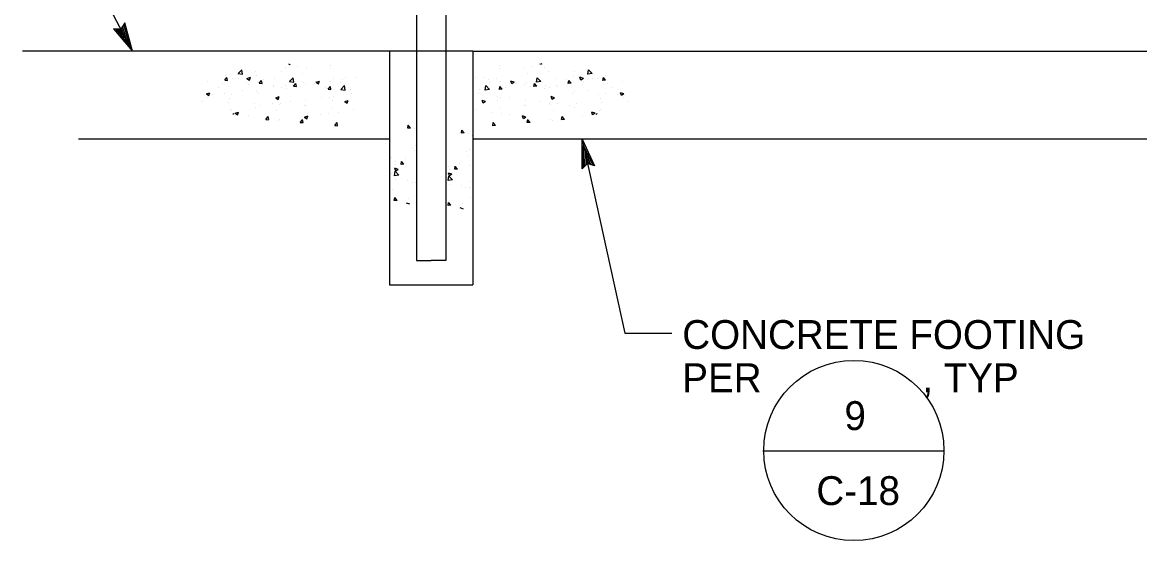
# Model space of a CAD drawing. Extents: x -123486 to -116575, y -107066 to -101122.
# Drawn here: x -118888.8 to -118656.4, y -103159.5 to -103051.7 of the extents above; entities that cross this region are included whole.
import ezdxf

# ---------------------------------------------------------------- set-up
doc = ezdxf.new("R2010")
doc.units = 0
for name, color, linetype in [('Erosion C (Lv35)', 7, 'Continuous'), ('G-MARK', 7, 'Continuous'), ('Misc CnstDet(22)', 7, 'Continuous')]:
    doc.layers.add(name, color=color, linetype=linetype)

# ---------------------------------------------------------------- blocks, each defined once
blk = doc.blocks.new('SC8415')
at = {"layer": 'Erosion C (Lv35)'}
for p, q in [((-1.69606, 1.76963), (-1.69579, 1.76945)), ((-1.69579, 1.76945), (-1.69573, 1.76963)), ((-1.69408, 1.76913), (-1.69408, 1.76913)), ((-1.68715, 1.76926), (-1.68715, 1.76926)), ((-1.70955, 1.76614), (-1.70906, 1.76672)), ((-1.70943, 1.76711), (-1.70943, 1.76711)), ((-1.70894, 1.76609), (-1.70906, 1.76672)), ((-1.70689, 1.76745), (-1.70689, 1.76745)), ((-1.70669, 1.76754), (-1.7059, 1.76836)), ((-1.70669, 1.76754), (-1.70579, 1.7674)), ((-1.70579, 1.7674), (-1.7059, 1.76836)), ((-1.70484, 1.76651), (-1.70412, 1.76679)), ((-1.70433, 1.76617), (-1.70412, 1.76679)), ((-1.70304, 1.76795), (-1.70304, 1.76795)), ((-1.70278, 1.76714), (-1.70278, 1.76714)), ((-1.6975, 1.7679), (-1.6975, 1.7679)), ((-1.69662, 1.7688), (-1.69662, 1.7688)), ((-1.69585, 1.76586), (-1.69506, 1.76668)), ((-1.69494, 1.76572), (-1.69506, 1.76668)), ((-1.69309, 1.7676), (-1.69309, 1.7676)), ((-1.69228, 1.76861), (-1.69228, 1.76861)), ((-1.68716, 1.76862), (-1.68716, 1.76862)), ((-1.68394, 1.76681), (-1.68394, 1.76681)), ((-1.682, 1.76664), (-1.682, 1.76664)), ((-1.71312, 1.76577), (-1.71312, 1.76577)), ((-1.71086, 1.76455), (-1.71086, 1.76455)), ((-1.71, 1.76543), (-1.71, 1.76543)), ((-1.70955, 1.76614), (-1.70894, 1.76608)), ((-1.70791, 1.76649), (-1.70791, 1.76649)), ((-1.70672, 1.76656), (-1.70672, 1.76656)), ((-1.70494, 1.76557), (-1.70494, 1.76557)), ((-1.70484, 1.76651), (-1.70433, 1.76617)), ((-1.70458, 1.7652), (-1.70458, 1.7652)), ((-1.70226, 1.7655), (-1.70177, 1.76608)), ((-1.70226, 1.7655), (-1.70165, 1.76545)), ((-1.70165, 1.76545), (-1.70177, 1.76609)), ((-1.7013, 1.76633), (-1.7013, 1.76633)), ((-1.6993, 1.76479), (-1.6993, 1.76479)), ((-1.69916, 1.76497), (-1.69916, 1.76497)), ((-1.69901, 1.76659), (-1.69901, 1.76659)), ((-1.69762, 1.76452), (-1.69762, 1.76452)), ((-1.69675, 1.76513), (-1.69675, 1.76513)), ((-1.69658, 1.76435), (-1.69658, 1.76435)), ((-1.69588, 1.7661), (-1.69588, 1.7661)), ((-1.69585, 1.76586), (-1.69494, 1.76572)), ((-1.69497, 1.76486), (-1.69449, 1.76545)), ((-1.69497, 1.76486), (-1.69437, 1.76481)), ((-1.69437, 1.76481), (-1.69448, 1.76545)), ((-1.69373, 1.76474), (-1.69373, 1.76474)), ((-1.6929, 1.76563), (-1.6929, 1.76563)), ((-1.69241, 1.76523), (-1.69241, 1.76523)), ((-1.69065, 1.76537), (-1.69065, 1.76537)), ((-1.69045, 1.76587), (-1.69045, 1.76587)), ((-1.69023, 1.7657), (-1.68952, 1.76597)), ((-1.69023, 1.7657), (-1.68973, 1.76536)), ((-1.68973, 1.76536), (-1.68952, 1.76597)), ((-1.68831, 1.76451), (-1.68831, 1.76451)), ((-1.68769, 1.76423), (-1.6872, 1.76481)), ((-1.68727, 1.76588), (-1.68727, 1.76588)), ((-1.68708, 1.76417), (-1.6872, 1.76481)), ((-1.68649, 1.76648), (-1.68649, 1.76648)), ((-1.68503, 1.76565), (-1.68503, 1.76565)), ((-1.685, 1.76418), (-1.68421, 1.765)), ((-1.68473, 1.76639), (-1.68473, 1.76639)), ((-1.6841, 1.76404), (-1.68421, 1.765)), ((-1.68289, 1.76428), (-1.68289, 1.76428)), ((-1.71337, 1.76324), (-1.71266, 1.76351)), ((-1.71337, 1.76324), (-1.71287, 1.7629)), ((-1.71325, 1.76239), (-1.71325, 1.76239)), ((-1.71287, 1.7629), (-1.71266, 1.76351)), ((-1.7121, 1.7631), (-1.7121, 1.7631)), ((-1.70956, 1.76344), (-1.70956, 1.76344)), ((-1.70843, 1.76232), (-1.70843, 1.76232)), ((-1.70803, 1.7631), (-1.70803, 1.7631)), ((-1.70571, 1.76395), (-1.70571, 1.76395)), ((-1.7029, 1.76375), (-1.7029, 1.76375)), ((-1.7025, 1.76334), (-1.7025, 1.76334)), ((-1.69877, 1.76242), (-1.69806, 1.7627)), ((-1.69877, 1.76242), (-1.69827, 1.76208)), ((-1.69826, 1.76208), (-1.69806, 1.7627)), ((-1.68916, 1.76247), (-1.68916, 1.76247)), ((-1.68769, 1.76423), (-1.68708, 1.76417)), ((-1.6874, 1.7625), (-1.6874, 1.7625)), ((-1.68662, 1.7628), (-1.68662, 1.7628)), ((-1.685, 1.76418), (-1.6841, 1.76404)), ((-1.68277, 1.76331), (-1.68277, 1.76331)), ((-1.71417, 1.76163), (-1.71417, 1.76163)), ((-1.70874, 1.7614), (-1.70874, 1.7614)), ((-1.70839, 1.75994), (-1.70839, 1.75994)), ((-1.70815, 1.75972), (-1.70815, 1.75972)), ((-1.70332, 1.76117), (-1.70332, 1.76117)), ((-1.70302, 1.76037), (-1.70302, 1.76037)), ((-1.70197, 1.76078), (-1.70197, 1.76078)), ((-1.69943, 1.76112), (-1.69943, 1.76112)), ((-1.69862, 1.75978), (-1.69862, 1.75978)), ((-1.6979, 1.76094), (-1.6979, 1.76094)), ((-1.69775, 1.76113), (-1.69775, 1.76113)), ((-1.69558, 1.76162), (-1.69558, 1.76162)), ((-1.6927, 1.7608), (-1.6927, 1.7608)), ((-1.69253, 1.76185), (-1.69253, 1.76185)), ((-1.69247, 1.76071), (-1.69247, 1.76071)), ((-1.68705, 1.76048), (-1.68705, 1.76048)), ((-1.68677, 1.76182), (-1.68677, 1.76182)), ((-1.68417, 1.76161), (-1.68346, 1.76188)), ((-1.68417, 1.76161), (-1.68366, 1.76127)), ((-1.68366, 1.76127), (-1.68346, 1.76188)), ((-1.68224, 1.75988), (-1.68224, 1.75988)), ((-1.70775, 1.75896), (-1.70765, 1.75908)), ((-1.70762, 1.7589), (-1.70765, 1.75908)), ((-1.70731, 1.75915), (-1.7066, 1.75942)), ((-1.70731, 1.75915), (-1.7068, 1.75881)), ((-1.7068, 1.75881), (-1.7066, 1.75942)), ((-1.70455, 1.75876), (-1.70455, 1.75876)), ((-1.70085, 1.75786), (-1.70036, 1.75844)), ((-1.70085, 1.75786), (-1.70025, 1.7578)), ((-1.70024, 1.75781), (-1.70036, 1.75844)), ((-1.69825, 1.75762), (-1.69825, 1.75762)), ((-1.69787, 1.75775), (-1.69787, 1.75775)), ((-1.69357, 1.75722), (-1.69308, 1.7578)), ((-1.69357, 1.75722), (-1.69296, 1.75717)), ((-1.69296, 1.75717), (-1.69307, 1.75781)), ((-1.69271, 1.75833), (-1.692, 1.75861)), ((-1.69271, 1.75833), (-1.6922, 1.75799)), ((-1.69265, 1.75847), (-1.69265, 1.75847)), ((-1.6922, 1.75799), (-1.69199, 1.75861)), ((-1.69183, 1.75846), (-1.69183, 1.75846)), ((-1.68929, 1.7588), (-1.68929, 1.7588)), ((-1.68752, 1.75912), (-1.68752, 1.75912)), ((-1.68544, 1.7593), (-1.68544, 1.7593)), ((-1.68628, 1.75658), (-1.68579, 1.75717)), ((-1.68628, 1.75658), (-1.68567, 1.75653)), ((-1.68567, 1.75653), (-1.68579, 1.75717))]:
    blk.add_line(p, q, dxfattribs=at)

msp = doc.modelspace()

# ---------------------------------------------------------------- linework, layer by layer
at = {"layer": 'G-MARK'}
for p, q in [((-118865.89, -103057.71), (-118875.41, -103039.76)), ((-118868.33, -103053.12), (-118869.89, -103053.04)), ((-118869.89, -103053.04), (-118869.89, -103053.04)), ((-118869.89, -103053.04), (-118865.89, -103057.71)), ((-118869.47, -103053.06), (-118866.54, -103056.49)), ((-118869.04, -103053.1), (-118867.19, -103055.27)), ((-118868.66, -103053.09), (-118867.84, -103054.05)), ((-118867.53, -103051.79), (-118868.33, -103053.12)), ((-118867.84, -103054.05), (-118868.17, -103052.86)), ((-118867.19, -103055.27), (-118867.96, -103052.48)), ((-118866.54, -103056.48), (-118867.74, -103052.16)), ((-118865.89, -103057.71), (-118867.53, -103051.79)), ((-118867.53, -103051.79), (-118867.53, -103051.79)), ((-118865.89, -103057.71), (-118865.89, -103057.71)), ((-118772.38, -103082.15), (-118772.36, -103076)), ((-118772.36, -103076), (-118763.49, -103116.38)), ((-118772.36, -103076), (-118772.36, -103076)), ((-118772.36, -103076), (-118769.77, -103081.57)), ((-118772.08, -103081.86), (-118772.06, -103077.35)), ((-118772.06, -103077.36), (-118770.17, -103081.42)), ((-118771.78, -103081.55), (-118771.77, -103078.7)), ((-118771.77, -103078.7), (-118770.55, -103081.32)), ((-118771.24, -103081.08), (-118772.38, -103082.15)), ((-118771.48, -103081.31), (-118771.47, -103080.05)), ((-118771.47, -103080.05), (-118770.95, -103081.17)), ((-118769.77, -103081.57), (-118771.24, -103081.08)), ((-118769.77, -103081.57), (-118769.77, -103081.57)), ((-118772.38, -103082.15), (-118772.38, -103082.15)), ((-118763.49, -103116.38), (-118753.69, -103116.38)), ((-118734.78, -103140.84), (-118697.08, -103140.84))]:
    msp.add_line(p, q, dxfattribs=at)
msp.add_circle((-118715.83, -103140.79), 18.75, dxfattribs=at)
at = {"layer": 'Misc CnstDet(22)'}
for p, q in [((-118800.72, -102947.98), (-118800.72, -103101.22)), ((-118806.81, -102960.17), (-118806.81, -103101.22)), ((-118812.43, -103057.71), (-118888.83, -103057.71)), ((-118855.01, -103057.71), (-118877.35, -103057.71)), ((-118875.63, -103057.71), (-118875.63, -103057.71)), ((-118855.01, -103057.71), (-118860.95, -103057.71)), ((-118859.24, -103057.71), (-118859.24, -103057.71)), ((-118853.29, -103057.71), (-118853.29, -103057.71)), ((-118853.29, -103057.71), (-118853.29, -103057.71)), ((-118812.43, -103057.71), (-118812.43, -103094.29)), ((-118795.1, -103057.71), (-118812.43, -103057.71)), ((-118795.1, -103057.71), (-118795.1, -103106.29)), ((-118795.1, -103057.71), (-118622.28, -103057.71)), ((-118808.66, -103073.75), (-118808.55, -103073.12)), ((-118808.06, -103073.69), (-118808.66, -103073.75)), ((-118808.06, -103073.69), (-118808.55, -103073.12)), ((-118807.17, -103073.89), (-118807.17, -103073.89)), ((-118797.49, -103074.76), (-118797.38, -103074.13)), ((-118796.89, -103074.71), (-118797.49, -103074.76)), ((-118796.89, -103074.71), (-118797.37, -103074.13)), ((-118812.43, -103076), (-118877.12, -103076)), ((-118812.24, -103076.47), (-118812.24, -103076.47)), ((-118796, -103074.91), (-118796, -103074.91)), ((-118795.27, -103075.21), (-118795.27, -103075.21)), ((-118623.66, -103076), (-118795.1, -103076)), ((-118807.6, -103077.64), (-118807.6, -103077.64)), ((-118807.33, -103078.38), (-118807.33, -103078.38)), ((-118807.05, -103077.22), (-118807.05, -103077.22)), ((-118796.43, -103078.65), (-118796.43, -103078.65)), ((-118795.88, -103078.24), (-118795.88, -103078.24)), ((-118812.12, -103079.8), (-118812.12, -103079.8)), ((-118811.29, -103080.75), (-118811.29, -103080.75)), ((-118811.15, -103081.38), (-118811.15, -103081.38)), ((-118810.05, -103081.27), (-118809.93, -103080.64)), ((-118809.45, -103081.22), (-118810.05, -103081.27)), ((-118809.45, -103081.22), (-118809.93, -103080.64)), ((-118809.72, -103080.57), (-118809.72, -103080.57)), ((-118809.04, -103080.04), (-118809.04, -103080.04)), ((-118806.93, -103080.55), (-118806.93, -103080.55)), ((-118798.88, -103082.28), (-118798.76, -103081.65)), ((-118798.28, -103082.23), (-118798.76, -103081.66)), ((-118798.55, -103081.59), (-118798.55, -103081.59)), ((-118797.87, -103081.05), (-118797.87, -103081.05)), ((-118796.16, -103079.39), (-118796.16, -103079.39)), ((-118795.76, -103081.57), (-118795.76, -103081.57)), ((-118812, -103083.13), (-118812, -103083.13)), ((-118811.39, -103083.61), (-118811.28, -103082.66)), ((-118810.5, -103083.48), (-118811.39, -103083.61)), ((-118811.13, -103082.64), (-118811.34, -103082.04)), ((-118810.63, -103082.31), (-118811.33, -103082.04)), ((-118810.5, -103083.48), (-118811.28, -103082.66)), ((-118810.63, -103082.31), (-118811.13, -103082.64)), ((-118806.81, -103083.88), (-118806.81, -103083.88)), ((-118800.22, -103084.63), (-118800.11, -103083.68)), ((-118799.46, -103083.32), (-118800.16, -103083.05)), ((-118799.96, -103083.65), (-118800.16, -103083.05)), ((-118800.11, -103081.76), (-118800.11, -103081.76)), ((-118799.33, -103084.49), (-118800.11, -103083.68)), ((-118799.98, -103082.4), (-118799.98, -103082.4)), ((-118799.46, -103083.32), (-118799.96, -103083.66)), ((-118798.28, -103082.23), (-118798.88, -103082.28)), ((-118812.39, -103085.35), (-118812.39, -103085.35)), ((-118811.16, -103084.37), (-118811.16, -103084.37)), ((-118808.65, -103084.69), (-118808.65, -103084.69)), ((-118807.71, -103085.07), (-118807.71, -103085.07)), ((-118807.06, -103085.12), (-118807.06, -103085.12)), ((-118799.33, -103084.49), (-118800.22, -103084.63)), ((-118799.99, -103085.38), (-118799.99, -103085.38)), ((-118797.48, -103085.71), (-118797.48, -103085.71)), ((-118796.54, -103086.09), (-118796.54, -103086.09)), ((-118795.88, -103086.14), (-118795.88, -103086.14)), ((-118795.63, -103084.89), (-118795.63, -103084.89)), ((-118812.32, -103087.81), (-118812.32, -103087.81)), ((-118811.88, -103086.46), (-118811.88, -103086.46)), ((-118811.44, -103088.79), (-118811.32, -103088.16)), ((-118810.84, -103088.74), (-118811.32, -103088.16)), ((-118808.53, -103088.31), (-118808.53, -103088.31)), ((-118806.68, -103087.21), (-118806.68, -103087.21)), ((-118795.51, -103088.22), (-118795.51, -103088.22)), ((-118810.84, -103088.74), (-118811.44, -103088.79)), ((-118808.2, -103089.56), (-118808.9, -103089.29)), ((-118800.27, -103089.8), (-118800.15, -103089.18)), ((-118799.67, -103089.75), (-118800.27, -103089.8)), ((-118799.67, -103089.75), (-118800.15, -103089.18)), ((-118797.03, -103090.57), (-118797.73, -103090.3)), ((-118797.36, -103089.32), (-118797.36, -103089.32)), ((-118812.43, -103094.29), (-118812.43, -103106.29)), ((-118806.81, -103101.22), (-118803.76, -103101.22)), ((-118800.72, -103101.22), (-118803.76, -103101.22)), ((-118812.43, -103106.29), (-118795.1, -103106.29))]:
    msp.add_line(p, q, dxfattribs=at)

# ---------------------------------------------------------------- block references
at = {"layer": 'Misc CnstDet(22)', "xscale": 984.251968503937, "yscale": 984.251968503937}
msp.add_blockref('SC8415', (-117164.11, -104802.07), dxfattribs=at)
at = {"layer": 'Misc CnstDet(22)', "xscale": 984.251968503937, "yscale": -984.251968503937, "rotation": 180}
msp.add_blockref('SC8415', (-120450.1, -104802.07), dxfattribs=at)

# ---------------------------------------------------------------- texts
at = {"layer": 'Misc CnstDet(22)'}
for s, p in [('CONCRETE FOOTING', (-118751.53, -103119.65)), ('PER               , TYP', (-118751.53, -103128.65)), ('9', (-118717.79, -103136.52)), ('C-18', (-118723.63, -103152.13))]:
    msp.add_text(s, height=6, dxfattribs=at).set_placement(p)

doc.saveas('drawing.dxf')
